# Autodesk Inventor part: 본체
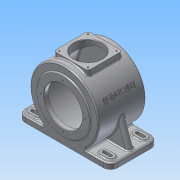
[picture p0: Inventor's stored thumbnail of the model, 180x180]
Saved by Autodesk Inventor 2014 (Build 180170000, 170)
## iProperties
Created: 2015-06
Part Number: 본체
Material: 알루미늄 6061
Document SubType Name: Modeling
Designer: Administrator
Density: 2.71 g/cm^3
Appearance: 알루미늄 - 평지
Mass: 3273.86 g
Surface Area: 2306.49 cm^2
Volume: 1208.06 cm^3
Author: Administrator
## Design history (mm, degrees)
sketch "스케치1"
  geometry: L1 (115, -59)-(-115, -59); L2 (-115, -59)-(-115, 59); L3 (-115, 59)-(115, 59); L4 (115, 59)-(115, -59); L5 (115, -59)-(-115, 59); L6 (-115, -59)-(115, 59); 1 further point
  constraints: 12 end point, 2 midpoint, 2 parallel, 1 horizontal, 1 perpendicular
  dimensions: "d0" = 230 distance of L2.end L3.end; "d1" = 118 distance of L1.end L2.end
extrude "돌출1" new body sketch "스케치1" distance "d2" = 14; taper "d3" = 0 deg
fillet "모깎기1" dims "d4" = 18
node "작업 평면1"
sketch "스케치2"
  geometry: L1 (194, 0)-(0, 0) reference; C1 r 65 at (97, 85); 1 further point
  constraints: 1 centre point, 1 vertical alignment
  dimensions: "d6" = 130 diameter of C1; "d7" = 85 distance from line of L1 C1.centre
extrude "돌출2" join sketch "스케치2" distance "d8" = 134; taper "d9" = 0 deg
sketch "스케치3"
  geometry: C1 r 65 at (97, 85) reference; C2 r 85 at (97, 85); 1 further point
  constraints: 1 centre point, 1 coincident
  dimensions: "d10" = 170 diameter of C2
extrude "돌출3" join sketch "스케치3" distance "d11" = 118; taper "d12" = 0 deg
node "작업 평면2"
sketch "스케치4"
  geometry: L1 (42.5, -42.5)-(-42.5, -42.5); L2 (-42.5, -42.5)-(-42.5, 42.5); L3 (-42.5, 42.5)-(42.5, 42.5); L4 (42.5, 42.5)-(42.5, -42.5); L5 (42.5, -42.5)-(-42.5, 42.5); L6 (-42.5, -42.5)-(42.5, 42.5); 1 further point
  constraints: 12 end point, 2 midpoint, 2 parallel, 2 perpendicular, 1 horizontal
  dimensions: "d14" = 85 distance of L2.end L3.end
extrude "돌출4" join sketch "스케치4" stored distance "d15" = 118; taper "d16" = 0 deg
hole "구멍1" diameter "d19" = 95; stored, may be unused: countersink angle "d23" = 90 deg, drill point angle "d25" = 0 deg; dims "d17" = 10, "d18" = 10, "d20" = 6, "d21" = 4, "d22" = 2, "d24" = 11
hole "구멍2" diameter "d28" = 154; stored, may be unused: countersink angle "d32" = 90 deg, drill point angle "d34" = 0 deg; dims "d29" = 6, "d30" = 154, "d31" = 102, "d33" = 102, "d113" = 10, "d114" = 10
sketch "스케치5"
  geometry: C1 r 35 at (0, 0); 1 further point
  constraints: 1 centre point, 1 coincident
  dimensions: "d44" = 70 diameter of C1
extrude "돌출5" cut sketch "스케치5" stored distance "d45" = 118; taper "d46" = 0 deg
sketch "스케치6"
  geometry: L1 (35.5, -35.5)-(-35.5, -35.5); L2 (-35.5, -35.5)-(-35.5, 35.5); L3 (-35.5, 35.5)-(35.5, 35.5); L4 (35.5, 35.5)-(35.5, -35.5); L5 (35.5, -35.5)-(-35.5, 35.5); L6 (-35.5, -35.5)-(35.5, 35.5); C1 r 35 at (0, 0) reference; 4 further points
  constraints: 12 end point, 4 coincident, 2 midpoint, 2 parallel, 2 perpendicular, 1 horizontal
  dimensions: "d47" = 71 distance of L2.end L3.end
hole "구멍4" sketch "스케치6" at (-35.5, 35.5), (-35.5, -35.5), (35.5, -35.5), (35.5, 35.5) diameter "d48" = 3.242; stored, may be unused: countersink angle "d52" = 90 deg, drill point angle "d54" = 118 deg; dims "d49" = 10, "d50" = 4, "d51" = 2, "d53" = 13
sketch "스케치7"
  geometry: C1 r 47.5 at (0, 0) reference; 2 further points
  constraints: 1 vertical alignment
  dimensions: "d55" = 55 distance of C1.centre point (0, 55)
hole "구멍5" sketch "스케치7" at (0, 55) diameter "d56" = 3.242; stored, may be unused: countersink angle "d60" = 90 deg, drill point angle "d62" = 118 deg; dims "d57" = 20, "d58" = 4, "d59" = 2, "d61" = 25
node "작업 평면3"
sketch "스케치8"
  geometry: L1 (0, 0)-(194, 0) reference; L2 (0, -14)-(0, 0) reference; L3 (50.267, -14)-(0, -14) reference; L4 (194, -14)-(143.733, -14) reference; L5 (194, 0)-(194, -14) reference; L6 (212, -14)-(194, -14) reference; L7 (0, -14)-(-18, -14) reference; L8 (-12, -14)-(12.13, -80.297); L9 (181.87, -80.297)-(206, -14); L10 (212, -14)-(212, 0) reference; L11 (-18, 0)-(-18, -14) reference; L12 (206, -14)-(143.733, -14); L13 (-12, -14)-(50.267, -14); C1 r 65 at (97, -85) reference; A1 r 85 centre (97, -85) between (50.267, -14) and (143.733, -14) reference; A2 r 85 centre (97, -85) between (181.87, -80.297) and (143.733, -14); A3 r 85 centre (97, -85) between (50.267, -14) and (12.13, -80.297); 1 further point
  constraints: 8 end point, 6 point on circle, 4 concentric, 2 centre point, 2 collinear, 2 point on line
  dimensions: "d68" = 110 deg angle of L7 L8; "d69" = 6 distance from line of L9.end L10; "d70" = 110 deg angle of L9 L6; "d71" = 6 distance from line of L11 L8.start
extrude "돌출6" join sketch "스케치8" stored distance "d72" = 15; taper "d73" = 0 deg
sketch "스케치9"
  geometry: L1 (-46.733, 59)-(-97, 59) reference; L2 (-97, 50)-(-81, 50); L3 (-81, 32)-(-97, 32); L4 (-97, -32)-(-81, -32); L5 (-81, -50)-(-97, -50); L6 (81, 50)-(97, 50); L7 (97, 32)-(81, 32); L8 (81, -32)-(97, -32); L9 (97, -50)-(81, -50); A1 r 18 centre (-97, 41) between (-97, 59) and (-115, 41) reference; A2 r 18 centre (-97, -41) between (-115, -41) and (-97, -59) reference; A3 r 9 centre (-81, 41) between (-81, 32) and (-81, 50); A4 r 9 centre (-97, 41) between (-97, 50) and (-97, 32); A5 r 9 centre (-97, -41) between (-97, -32) and (-97, -50); A6 r 9 centre (-81, -41) between (-81, -50) and (-81, -32); A7 r 9 centre (81, 41) between (81, 50) and (81, 32); A8 r 9 centre (97, 41) between (97, 32) and (97, 50); A9 r 9 centre (81, -41) between (81, -32) and (81, -50); A10 r 9 centre (97, -41) between (97, -50) and (97, -32); A11 r 18 centre (97, 41) between (115, 41) and (97, 59) reference; A12 r 18 centre (97, -41) between (97, -59) and (115, -41) reference; 1 further point
  constraints: 16 end point, 16 point on circle, 16 tangent, 8 centre point, 4 coincident, 4 horizontal alignment, 2 parallel
  dimensions: "d74" = 16 distance of L2.start L2.end; "d75" = 18 distance between parallel lines of L3 L2; "d77" = 16 distance of L4.start L4.end; "d78" = 18 distance between parallel lines of L5 L4; "d79" = 16 distance of L6.start L6.end; "d80" = 18 distance between parallel lines of L7 L6; "d81" = 16 distance of L8.start L8.end; "d82" = 18 distance between parallel lines of L9 L8
extrude "돌출7" join sketch "스케치9" distance "d83" = 3; taper "d84" = 0 deg
sketch "스케치10"
  geometry: L1 (-81, 50)-(-97, 50) reference; L2 (-97, 32)-(-81, 32) reference; L3 (-97, 45)-(-81, 45); L4 (-81, 37)-(-97, 37); L5 (-81, -32)-(-97, -32) reference; L6 (-97, -50)-(-81, -50) reference; L7 (97, 50)-(81, 50) reference; L8 (81, 32)-(97, 32) reference; L9 (97, -32)-(81, -32) reference; L10 (81, -50)-(97, -50) reference; L11 (-97, -37)-(-81, -37); L12 (-81, -45)-(-97, -45); L13 (81, -37)-(97, -37); L14 (97, -45)-(81, -45); L15 (81, 45)-(97, 45); L16 (97, 37)-(81, 37); A1 r 9 centre (-97, 41) between (-97, 50) and (-97, 32) reference; A2 r 9 centre (-81, 41) between (-81, 32) and (-81, 50) reference; A3 r 4 centre (-81, 41) between (-81, 37) and (-81, 45); A4 r 4 centre (-97, 41) between (-97, 45) and (-97, 37); A5 r 9 centre (-97, -41) between (-97, -32) and (-97, -50) reference; A6 r 9 centre (-81, -41) between (-81, -50) and (-81, -32) reference; A7 r 9 centre (81, 41) between (81, 50) and (81, 32) reference; A8 r 9 centre (97, 41) between (97, 32) and (97, 50) reference; A9 r 9 centre (81, -41) between (81, -32) and (81, -50) reference; A10 r 9 centre (97, -41) between (97, -50) and (97, -32) reference; A11 r 4 centre (-81, -41) between (-81, -45) and (-81, -37); A12 r 4 centre (-97, -41) between (-97, -37) and (-97, -45); A13 r 4 centre (97, -41) between (97, -45) and (97, -37); A14 r 4 centre (81, -41) between (81, -37) and (81, -45); A15 r 4 centre (97, 41) between (97, 37) and (97, 45); A16 r 4 centre (81, 41) between (81, 45) and (81, 37); 1 further point
  constraints: 16 end point, 16 point on circle, 8 centre point, 12 other
  dimensions: "d85" = 8 distance between parallel lines of L4 L3; "d86" = 8 distance between parallel lines of L12 L11; "d87" = 8 distance between parallel lines of L14 L13; "d88" = 8 distance between parallel lines of L16 L15
extrude "돌출8" cut sketch "스케치10" stored distance "d89" = 3; taper "d90" = 0 deg
sketch "스케치11"
  geometry: L1 (97, -85)-(19.964, -120.923); A1 r 85 centre (97, -85) between (50.267, -14) and (143.733, -14) reference; 3 further points
  constraints: 2 end point, 2 point on circle, 1 coincident, 1 horizontal alignment
  dimensions: "d91" = 25 deg dimension on L1.start L1.end point (12, -85)
node "작업 평면4"
sketch "스케치12"
  geometry: L1 (-62, 65)-(-62, -65) reference; L2 (-59, 65)-(-59, -65) reference; L3 (-59, -118.03)-(-59, -36.042) reference; L4 (-59, -105.342)-(-59, -118.03) reference; L5 (-59, -84.098)-(-59, -105.342) reference; L6 (-59, -84.098)-(-59, -44.598) reference; L7 (-59, -23.354)-(-59, -44.598) reference; L8 (-59, -36.042)-(-59, -23.354) reference; 4 further points
  constraints: 1 coincident, 1 other
  dimensions: "d92" = 59 distance from line of point (0, 0) L2; "d93" = 23.354 vertical distance of L7.start point (0, 0)
feature "엠보싱1" sketch "스케치12" dims "d94" = 0.5, "d95" = 0
fillet "모깎기2" dims "d96" = 3
fillet "모깎기4" dims "d98" = 3
fillet "모깎기6" dims "d100" = 7
fillet "모깎기9" dims "d103" = 3
fillet "모깎기20" dims "d135" = 7.5
fillet "모깎기21" dims "d136" = 3
fillet "모깎기18" dims "d133" = 3
fillet "모깎기14" dims "d108" = 3
fillet "모깎기15" dims "d109" = 3
chamfer "모따기1" distance "d110" = 1; stored, may be unused: second distance "d111" = 2, angle "d112" = 45 deg
sketch "스케치13"
  geometry: C1 r 74 at (0, 0) reference; C2 r 31 at (0, 0); 1 further point
  constraints: 1 centre point, 1 coincident
  dimensions: "d115" = 62 diameter of C2
extrude "돌출9" join sketch "스케치13" distance "d116" = 3.5; taper "d117" = -25 deg
hole "구멍6" diameter "d120" = 30; stored, may be unused: countersink angle "d124" = 90 deg, drill point angle "d126" = 0 deg; dims "d118" = 10, "d119" = 10, "d121" = 30, "d122" = 47, "d123" = 14, "d125" = 3
fillet "모깎기16" dims "d127" = 3, "d128" = 0.3
fillet "모깎기17" dims "d129" = 3
chamfer "모따기2" distance "d130" = 1; stored, may be unused: second distance "d131" = 2, angle "d132" = 45 deg
fillet "모깎기22" dims "d137" = 3
fillet "모깎기23" dims "d138" = 3
node "솔리드1"
pattern_circular "원형 패턴1" dims angle "d64" = 360 deg
node "투영된 루프1"
node "투영된 루프2"
node "투영된 루프3"
node "투영된 루프4"
node "투영된 루프5"
other parameters: "d5" = 13, "d13" = -173, "d66" = -59
